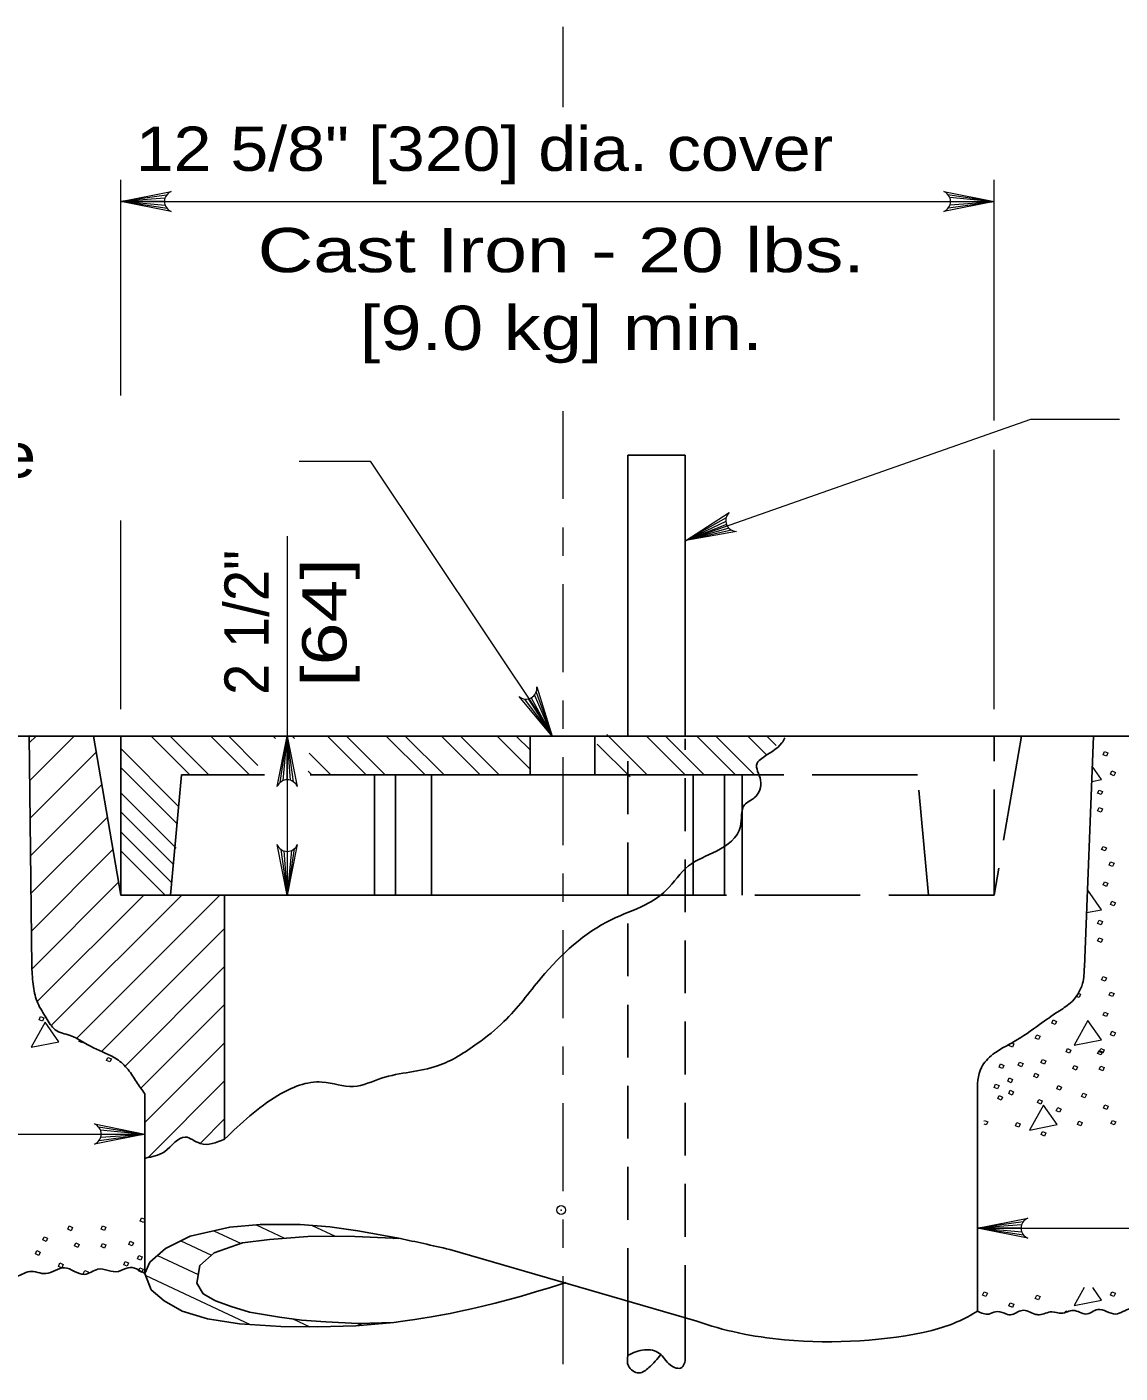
# Model space of a CAD drawing. Extents: x 1083.1 to 1117.1, y 719.4 to 741.4.
# Drawn here: x 1100.181 to 1104.035, y 731.723 to 736.468 of the extents above; entities that cross this region are included whole.
import ezdxf
from ezdxf.enums import TextEntityAlignment as Align

# ---------------------------------------------------------------- set-up
doc = ezdxf.new("R2010")
doc.units = 0
doc.header["$LTSCALE"] = 0.062
doc.header["$PDMODE"] = 32
doc.header["$PDSIZE"] = 0.031
for name, pattern in [('DOT_DASHED', [7.7, 5, -1.2, 0.3, -1.2]), ('LONG_DASHED', [7.5, 6, -1.5]), ('MEDIUM_DASHED', [4.5, 3, -1.5])]:
    doc.linetypes.add(name, pattern=pattern)
doc.layers.add('1', color=7, linetype='Continuous', lineweight=13)

msp = doc.modelspace()

# ---------------------------------------------------------------- linework, layer by layer
at = {"layer": '1'}
for p, q in [((1102.07067, 736.18433), (1102.07067, 736.46758)), ((1100.51158, 735.16817), (1100.51158, 735.92842)), ((1103.59067, 735.08033), (1103.59067, 735.92842)), ((1100.67275, 735.875), (1100.51158, 735.85242)), ((1100.66733, 735.86383), (1100.51158, 735.85242)), ((1103.42758, 735.87733), (1103.59067, 735.85242)), ((1103.43375, 735.86692), (1103.59067, 735.85242)), ((1100.51158, 735.85242), (1103.59067, 735.85242)), ((1100.66567, 735.85242), (1100.51158, 735.85242)), ((1100.6685, 735.83792), (1100.51158, 735.85242)), ((1100.67467, 735.8275), (1100.51158, 735.85242)), ((1103.4295, 735.82983), (1103.59067, 735.85242)), ((1103.43492, 735.841), (1103.59067, 735.85242)), ((1103.43658, 735.85242), (1103.59067, 735.85242)), ((1103.59067, 734.06258), (1103.59067, 734.97675)), ((1100.51158, 734.06258), (1100.51158, 734.72783)), ((1102.64525, 734.73708), (1102.50367, 734.65683)), ((1102.64433, 734.72475), (1102.50367, 734.65683)), ((1101.09833, 734.67275), (1101.09833, 733.40725)), ((1102.647, 734.7135), (1102.50367, 734.65683)), ((1102.65492, 734.70108), (1102.50367, 734.65683)), ((1102.6645, 734.69367), (1102.50367, 734.65683)), ((1101.95842, 734.103), (1102.032, 733.96767)), ((1101.96967, 734.11242), (1102.032, 733.96767)), ((1101.97592, 734.12283), (1102.032, 733.96767)), ((1101.93508, 734.0985), (1102.032, 733.96767)), ((1101.9475, 734.099), (1102.032, 733.96767)), ((1100.18842, 733.97), (1100.19267, 733.96767)), ((1100.18875, 733.94375), (1100.21267, 733.96767)), ((1100.19033, 733.811), (1100.34692, 733.96767)), ((1100.61842, 733.96767), (1100.75508, 733.831)), ((1100.68567, 733.96767), (1100.82233, 733.831)), ((1100.82908, 733.96767), (1100.96567, 733.831)), ((1100.892, 733.96767), (1100.99517, 733.86458)), ((1101.04842, 733.96767), (1101.05667, 733.95942)), ((1101.07342, 733.80458), (1101.09833, 733.96767)), ((1101.08383, 733.81075), (1101.09833, 733.96767)), ((1101.09833, 733.81367), (1101.09833, 733.96767)), ((1101.10975, 733.812), (1101.09833, 733.96767)), ((1101.12092, 733.8065), (1101.09833, 733.96767)), ((1101.1155, 733.96767), (1101.1235, 733.95967)), ((1101.24008, 733.96767), (1101.37667, 733.831)), ((1101.30717, 733.96767), (1101.44383, 733.831)), ((1101.4475, 733.96767), (1101.58417, 733.831)), ((1101.51458, 733.96767), (1101.65125, 733.831)), ((1101.642, 733.96767), (1101.77867, 733.831)), ((1101.70908, 733.96767), (1101.84575, 733.831)), ((1101.83842, 733.96767), (1101.95433, 733.85175)), ((1101.9055, 733.96767), (1101.95433, 733.91883)), ((1102.22458, 733.97342), (1102.36692, 733.831)), ((1102.36492, 733.96767), (1102.50158, 733.831)), ((1102.43208, 733.96767), (1102.56867, 733.831)), ((1102.542, 733.96767), (1102.67867, 733.831)), ((1102.60917, 733.96767), (1102.74583, 733.831)), ((1102.72183, 733.96767), (1102.78867, 733.90083)), ((1102.78892, 733.96767), (1102.82225, 733.93433)), ((1100.51158, 733.92383), (1100.7155, 733.71992)), ((1102.191, 733.93983), (1102.30692, 733.82392)), ((1100.19192, 733.67833), (1100.42533, 733.91175)), ((1101.17592, 733.90725), (1101.25217, 733.831)), ((1100.51158, 733.85658), (1100.70992, 733.65825)), ((1100.72542, 733.83042), (1100.72442, 733.8285)), ((1101.17217, 733.84392), (1101.18508, 733.831)), ((1100.19342, 733.54567), (1100.44492, 733.79708)), ((1100.51158, 733.76817), (1100.70717, 733.57258)), ((1100.195, 733.413), (1100.4645, 733.68242)), ((1100.51158, 733.70092), (1100.69708, 733.51542)), ((1100.51158, 733.63075), (1100.69125, 733.45108)), ((1100.19658, 733.28025), (1100.48408, 733.56783)), ((1100.51158, 733.5635), (1100.66783, 733.40725)), ((1101.07575, 733.56842), (1101.09833, 733.40725)), ((1101.08692, 733.563), (1101.09833, 733.40725)), ((1101.12325, 733.57033), (1101.09833, 733.40725)), ((1101.11283, 733.56417), (1101.09833, 733.40725)), ((1101.09833, 733.56133), (1101.09833, 733.40725)), ((1100.19858, 733.148), (1100.50375, 733.45308)), ((1100.21692, 733.03208), (1100.59225, 733.40725)), ((1100.2665, 732.94733), (1100.7265, 733.40725)), ((1100.35458, 732.90108), (1100.86075, 733.40725)), ((1103.92133, 733.42483), (1103.91908, 733.42075)), ((1100.44325, 732.85558), (1100.87758, 733.28975)), ((1100.52667, 732.80467), (1100.87758, 733.1555)), ((1100.58275, 732.72642), (1100.87758, 733.02125)), ((1100.59642, 732.60583), (1100.87758, 732.887)), ((1100.60867, 732.48383), (1100.87758, 732.75267)), ((1100.43333, 732.59008), (1100.59642, 732.56517)), ((1100.79142, 732.53233), (1100.87758, 732.61842)), ((1103.55483, 732.6105), (1103.55625, 732.61325)), ((1098.15858, 732.56517), (1100.59642, 732.56517)), ((1100.43525, 732.54267), (1100.59642, 732.56517)), ((1100.4395, 732.57967), (1100.59642, 732.56517)), ((1100.44067, 732.55375), (1100.59642, 732.56517)), ((1100.44233, 732.56517), (1100.59642, 732.56517)), ((1100.58508, 732.26958), (1100.59642, 732.26508)), ((1103.69258, 732.25592), (1103.53142, 732.23342)), ((1100.83983, 732.22417), (1100.93558, 732.17942)), ((1100.98858, 732.24475), (1101.08908, 732.19783)), ((1101.18608, 732.24267), (1101.26692, 732.20475)), ((1103.68708, 732.24475), (1103.53142, 732.23342)), ((1103.53142, 732.23342), (1105.67708, 732.23342)), ((1103.6855, 732.23342), (1103.53142, 732.23342)), ((1103.68833, 732.21892), (1103.53142, 732.23342)), ((1103.6945, 732.20842), (1103.53142, 732.23342)), ((1100.72325, 732.1885), (1100.83175, 732.13767)), ((1101.46542, 732.20225), (1101.47575, 732.19742)), ((1101.48958, 732.19792), (1101.49208, 732.19667)), ((1100.64125, 732.1365), (1100.78458, 732.0695)), ((1100.5995, 732.06592), (1100.96775, 731.89342)), ((1103.53133, 731.94125), (1103.53142, 731.94125)), ((1103.84067, 731.9365), (1103.843, 731.94208)), ((1103.843, 731.94208), (1103.85008, 731.93875)), ((1101.11867, 731.91325), (1101.17817, 731.88533)), ((1101.34408, 731.89792), (1101.35925, 731.89083)), ((1101.34992, 731.89783), (1101.36417, 731.89125)), ((1101.426, 731.89983), (1101.43142, 731.89733))]:
    msp.add_line(p, q, dxfattribs=at)
at = {"layer": '1', "linetype": 'DOT_DASHED'}
msp.add_line((1102.07067, 731.75358), (1102.07067, 735.13175), dxfattribs=at)
at = {"layer": '1', "lineweight": 25}
for p, q in [((1102.29925, 734.95792), (1102.50175, 734.95792)), ((1102.29925, 733.97167), (1102.29925, 734.95792)), ((1102.50175, 733.96933), (1102.50175, 734.95792)), ((1100.18842, 733.97), (1100.19808, 733.15417)), ((1100.41575, 733.96767), (1100.19267, 733.96767)), ((1103.94058, 733.96767), (1100.41575, 733.96767)), ((1100.51158, 733.40725), (1100.51158, 733.96767)), ((1101.95433, 733.831), (1101.95433, 733.96767)), ((1102.18225, 733.831), (1102.18225, 733.96767)), ((1100.68733, 733.40725), (1100.7255, 733.831)), ((1101.01833, 733.831), (1100.7255, 733.831)), ((1102.7635, 733.831), (1101.17875, 733.831)), ((1101.40542, 733.40725), (1101.40542, 733.831)), ((1101.4795, 733.40725), (1101.4795, 733.831)), ((1101.60683, 733.40725), (1101.60683, 733.831)), ((1102.52992, 733.52158), (1102.52992, 733.831)), ((1102.64008, 733.58558), (1102.64008, 733.831)), ((1102.70225, 733.6645), (1102.70225, 733.831)), ((1102.41183, 733.40725), (1100.87758, 733.40725)), ((1100.59642, 732.70692), (1100.59642, 732.48175)), ((1100.59642, 732.07317), (1100.59642, 732.48175)), ((1101.67142, 732.15792), (1102.54283, 731.9055)), ((1102.29925, 731.97708), (1102.29925, 731.78)), ((1102.50175, 731.91725), (1102.50175, 731.76733))]:
    msp.add_line(p, q, dxfattribs=at)
at = {"layer": '1', "linetype": 'MEDIUM_DASHED', "lineweight": 25}
for p, q in [((1102.29925, 731.97708), (1102.29925, 733.96033)), ((1102.50175, 731.91725), (1102.50175, 733.95808))]:
    msp.add_line(p, q, dxfattribs=at)
at = {"layer": '1', "linetype": 'LONG_DASHED', "lineweight": 25}
for p, q in [((1103.32067, 733.831), (1102.7635, 733.831)), ((1103.35883, 733.40725), (1103.32067, 733.831)), ((1102.70225, 733.40725), (1102.70225, 733.6645)), ((1102.64008, 733.40725), (1102.64008, 733.58558)), ((1102.52992, 733.40725), (1102.52992, 733.52158)), ((1103.59067, 733.40725), (1102.41183, 733.40725))]:
    msp.add_line(p, q, dxfattribs=at)
at = {"layer": '1'}
for points in [[(1100.68958, 735.81683), (1100.51158, 735.85242), (1100.68958, 735.888)], [(1103.41258, 735.888), (1103.59067, 735.85242), (1103.41258, 735.81683)], [(1102.5295, 734.66708), (1103.71983, 735.08525), (1104.03292, 735.08525)], [(1101.14017, 734.937), (1101.39058, 734.937), (1102.00717, 734.01325)], [(1102.68233, 734.68917), (1102.50367, 734.65683), (1102.65617, 734.7555)], [(1101.97817, 734.14108), (1102.032, 733.96767), (1101.91567, 734.10708)], [(1101.06275, 733.78967), (1101.09833, 733.96767), (1101.13392, 733.78967)], [(1104.00767, 733.96767), (1104.00758, 733.96758), (1104.00733, 733.96767)], [(1103.93433, 733.808), (1103.96958, 733.81492), (1103.93642, 733.86225)], [(1101.13392, 733.58525), (1101.09833, 733.40725), (1101.06275, 733.58525)], [(1103.916, 733.34558), (1103.96958, 733.356), (1103.92133, 733.42483)], [(1100.196, 733.331), (1100.19575, 733.33058), (1100.196, 733.33067)], [(1103.90867, 733.15725), (1103.91025, 733.15658), (1103.90833, 733.1525)], [(1103.88892, 733.06025), (1103.89525, 733.05767), (1103.8905, 733.04667), (1103.88125, 733.05033)], [(1100.37783, 732.88875), (1100.377, 732.88675), (1100.36508, 732.8915), (1100.3665, 732.89475)], [(1103.65292, 732.88625), (1103.65942, 732.88367), (1103.65467, 732.87175), (1103.64283, 732.87733), (1103.64442, 732.881)], [(1100.41833, 732.60075), (1100.59642, 732.56517), (1100.41833, 732.52958)], [(1103.55625, 732.61325), (1103.56808, 732.6085), (1103.56258, 732.59742), (1103.55483, 732.6005)], [(1100.59642, 732.2635), (1100.59225, 732.253), (1100.58033, 732.2585), (1100.58508, 732.26958)], [(1103.70942, 732.19775), (1103.53142, 732.23342), (1103.70942, 732.269)], [(1100.38367, 732.0705), (1100.37933, 732.07258), (1100.38492, 732.08367)], [(1100.38492, 732.08367), (1100.39675, 732.07892), (1100.39483, 732.07475)], [(1103.908, 732.02417), (1103.87225, 731.96033), (1103.96958, 731.97925), (1103.93808, 732.02417)]]:
    msp.add_lwpolyline(points, dxfattribs=at)
at = {"layer": '1', "lineweight": 25}
for points in [[(1100.19267, 733.96767), (1099.86592, 733.96767), (1099.63708, 733.6935)], [(1100.87758, 732.54725), (1100.87758, 733.40725), (1100.51158, 733.40725), (1100.41575, 733.96767)], [(1103.9085, 733.15417), (1103.94058, 733.96767), (1104.26742, 733.96767), (1104.47725, 733.6935)], [(1103.53142, 731.94125), (1103.53142, 732.02417), (1103.53142, 732.70692)], [(1101.4975, 732.19642), (1101.34708, 732.22383), (1101.249, 732.2375), (1101.14375, 732.24625), (1101.003, 732.24583), (1100.89567, 732.23708), (1100.75608, 732.20508), (1100.66917, 732.1615), (1100.61442, 732.11292), (1100.5965, 732.07325), (1100.61842, 732.0165), (1100.66483, 731.9775), (1100.72833, 731.94133), (1100.81742, 731.91392), (1100.92967, 731.89575), (1101.07542, 731.88675), (1101.20608, 731.885), (1101.33983, 731.88908), (1101.47467, 731.90117)], [(1101.47467, 731.90117), (1101.34775, 731.89783), (1101.235, 731.90292), (1101.14875, 731.90917), (1101.07117, 731.91958), (1100.96508, 731.93708), (1100.90092, 731.95675), (1100.84567, 731.9775), (1100.8015, 732.00242), (1100.77933, 732.03958), (1100.79025, 732.10158), (1100.84125, 732.14625), (1100.94075, 732.18125), (1101.03583, 732.19375), (1101.17075, 732.20408), (1101.31017, 732.20508), (1101.4975, 732.19642)]]:
    msp.add_lwpolyline(points, dxfattribs=at)
at = {"layer": '1', "linetype": 'LONG_DASHED', "lineweight": 25}
msp.add_lwpolyline([(1103.6865, 733.96767), (1103.59067, 733.40725), (1103.59067, 733.96767)], dxfattribs=at)
at = {"layer": '1'}
for points in [[(1103.97992, 733.913), (1103.99175, 733.90825), (1103.987, 733.89717), (1103.97517, 733.90192)], [(1104.006, 733.845), (1104.01792, 733.83942), (1104.01233, 733.82833), (1104.0005, 733.83308)], [(1103.96092, 733.77775), (1103.97275, 733.773), (1103.96725, 733.76192), (1103.95533, 733.76667)], [(1103.96092, 733.716), (1103.97275, 733.71125), (1103.96725, 733.69942), (1103.95533, 733.70492)], [(1103.97433, 733.57908), (1103.98625, 733.57433), (1103.9815, 733.56333), (1103.96958, 733.568)], [(1104.00125, 733.5245), (1104.01317, 733.51975), (1104.00758, 733.50867), (1103.99575, 733.51342)], [(1103.97992, 733.45408), (1103.99175, 733.44933), (1103.987, 733.43825), (1103.97517, 733.443)], [(1104.006, 733.38608), (1104.01792, 733.3805), (1104.01233, 733.36942), (1104.0005, 733.37417)], [(1103.96092, 733.31883), (1103.97275, 733.31408), (1103.96725, 733.303), (1103.95533, 733.30775)], [(1103.96092, 733.25708), (1103.97275, 733.25233), (1103.96725, 733.2405), (1103.95533, 733.246)], [(1103.97433, 733.12025), (1103.98625, 733.1155), (1103.9815, 733.10442), (1103.96958, 733.10917)], [(1104.00125, 733.06558), (1104.01317, 733.06083), (1104.00758, 733.04983), (1103.99575, 733.0545)], [(1100.22825, 732.97933), (1100.24008, 732.97458), (1100.23533, 732.96267), (1100.2235, 732.96825)], [(1103.79867, 732.9675), (1103.81058, 732.962), (1103.80583, 732.95092), (1103.79392, 732.95567)], [(1103.92133, 732.96592), (1103.87225, 732.87808), (1103.96958, 732.89708)], [(1103.97992, 732.99517), (1103.99175, 732.99042), (1103.987, 732.97942), (1103.97517, 732.98408)], [(1100.24483, 732.9595), (1100.19575, 732.87167), (1100.29308, 732.89067)], [(1104.006, 732.92717), (1104.01792, 732.92158), (1104.01233, 732.9105), (1104.0005, 732.91525)], [(1103.74092, 732.9145), (1103.75283, 732.90975), (1103.74725, 732.89867), (1103.73542, 732.90342)], [(1100.46642, 732.83533), (1100.47825, 732.83058), (1100.4735, 732.8195), (1100.46167, 732.82425)], [(1103.76117, 732.82842), (1103.773, 732.82292), (1103.7675, 732.81183), (1103.75558, 732.81733)], [(1103.849, 732.86642), (1103.86083, 732.86083), (1103.85608, 732.84983), (1103.84425, 732.85458)], [(1103.96092, 732.85992), (1103.97275, 732.85517), (1103.96725, 732.84408), (1103.95533, 732.84883)], [(1103.96692, 732.86642), (1103.97875, 732.86167), (1103.97325, 732.85058), (1103.96133, 732.85533)], [(1103.61317, 732.81258), (1103.62508, 732.80708), (1103.62033, 732.796), (1103.60842, 732.80075)], [(1103.68042, 732.81892), (1103.69233, 732.81417), (1103.68675, 732.80233), (1103.67492, 732.80783)], [(1103.73508, 732.77942), (1103.74692, 732.77383), (1103.74217, 732.76275), (1103.73033, 732.76833)], [(1103.87275, 732.80708), (1103.88458, 732.8015), (1103.87983, 732.7905), (1103.868, 732.796)], [(1103.96692, 732.80467), (1103.97875, 732.79992), (1103.97325, 732.78808), (1103.96133, 732.79358)], [(1103.59575, 732.74058), (1103.60767, 732.73583), (1103.60292, 732.72475), (1103.591, 732.7295)], [(1103.64325, 732.76275), (1103.65517, 732.75725), (1103.65042, 732.74617), (1103.6385, 732.75092)], [(1103.81575, 732.73583), (1103.82767, 732.73033), (1103.82292, 732.71925), (1103.811, 732.724)], [(1103.60842, 732.70108), (1103.62033, 732.6955), (1103.61558, 732.68442), (1103.60367, 732.69)], [(1103.64725, 732.71925), (1103.65908, 732.71367), (1103.65433, 732.70267), (1103.6425, 732.70817)], [(1103.74775, 732.68683), (1103.75958, 732.68208), (1103.75483, 732.67017), (1103.74292, 732.67575)], [(1103.90442, 732.709), (1103.91625, 732.70425), (1103.91075, 732.69233), (1103.89883, 732.69792)], [(1103.76433, 732.667), (1103.71525, 732.57917), (1103.81258, 732.59817)], [(1103.815, 732.65833), (1103.82683, 732.65275), (1103.82133, 732.64175), (1103.80942, 732.64642)], [(1103.98033, 732.66783), (1103.99225, 732.66308), (1103.9875, 732.652), (1103.97558, 732.65675)], [(1103.67092, 732.60533), (1103.68283, 732.60058), (1103.67725, 732.5895), (1103.66542, 732.59425)], [(1103.88933, 732.61008), (1103.90125, 732.60533), (1103.8965, 732.59425), (1103.88458, 732.599)], [(1104.00725, 732.61325), (1104.01908, 732.6085), (1104.01358, 732.59742), (1104.00175, 732.60217)], [(1103.76117, 732.57442), (1103.773, 732.56967), (1103.76825, 732.55783), (1103.75642, 732.56342)], [(1100.3295, 732.24108), (1100.34133, 732.23558), (1100.33658, 732.2245), (1100.32475, 732.22925)], [(1100.44742, 732.24108), (1100.45925, 732.23633), (1100.45375, 732.22525), (1100.44183, 732.23)], [(1100.24167, 732.20308), (1100.2535, 732.19758), (1100.248, 732.1865), (1100.23617, 732.19208)], [(1100.35325, 732.18175), (1100.36508, 732.17625), (1100.36033, 732.16517), (1100.3485, 732.17067)], [(1100.44742, 732.17942), (1100.45925, 732.17467), (1100.45375, 732.16275), (1100.44183, 732.16833)], [(1100.54475, 732.18733), (1100.55658, 732.18175), (1100.55183, 732.17067), (1100.54, 732.17542)], [(1100.21558, 732.15408), (1100.22742, 732.1485), (1100.22267, 732.13742), (1100.21083, 732.143)], [(1100.29625, 732.11058), (1100.30817, 732.105), (1100.30342, 732.09392), (1100.2915, 732.09867)], [(1100.52733, 732.11533), (1100.53917, 732.11058), (1100.53442, 732.0995), (1100.52258, 732.10425)], [(1100.57483, 732.13742), (1100.58667, 732.13192), (1100.58192, 732.12083), (1100.57008, 732.12558)], [(1100.57875, 732.09392), (1100.59067, 732.08842), (1100.58592, 732.07733), (1100.574, 732.08283)], [(1103.555, 732.00933), (1103.56683, 732.00383), (1103.56133, 731.99275), (1103.54942, 731.9975)], [(1103.64758, 731.97058), (1103.65942, 731.96583), (1103.65467, 731.954), (1103.64283, 731.9595)], [(1103.74092, 731.99667), (1103.75283, 731.99192), (1103.74725, 731.98083), (1103.73542, 731.98558)], [(1104.006, 732.00933), (1104.01792, 732.00383), (1104.01233, 731.99275), (1104.0005, 731.9975)]]:
    msp.add_lwpolyline(points, close=True, dxfattribs=at)
for centre, major_axis, start_param, end_param in [((1100.70407, 735.85242), (-0.03843, 0), 5.0978942, 7.4685073), ((1103.39817, 735.85242), (0.03843, 0), 5.0978942, 7.4685073), ((1102.68269, 734.72765), (-0.03625, -0.01274), 5.1365998, 7.5072129), ((1101.94001, 734.13676), (-0.03843, 0), 0.8835974, 3.2542105), ((1101.09832, 733.77521), (0.03843, 0), 0.3855052, 2.7561184), ((1101.09832, 733.59974), (-0.03843, 0), 0.3855052, 2.7561184), ((1100.40391, 732.56518), (0.03843, 0), 5.0978942, 7.4685073), ((1103.72388, 732.23338), (-0.03843, 0), 5.0978942, 7.4685073)]:
    msp.add_ellipse(centre, major_axis=major_axis, ratio=0.999895, start_param=start_param, end_param=end_param, dxfattribs=at)
at = {"layer": '1', "lineweight": 25}
for centre, major_axis, start_param, end_param in [((1103.12612, 732.07329), (0.49387, 0), 5.2308377, 5.6746503), ((1102.995, 732.1793), (-0.73959, 0), 0.9130573, 1.3757934), ((1103.00777, 732.21583), (-0.81859, 0), 1.3789738, 2.0303511)]:
    msp.add_ellipse(centre, major_axis=major_axis, ratio=0.467827, start_param=start_param, end_param=end_param, dxfattribs=at)
for points in [[(1102.85292, 733.96175), (1102.84217, 733.94383), (1102.77133, 733.88933), (1102.75508, 733.87217), (1102.76733, 733.81217), (1102.745, 733.75067), (1102.71092, 733.7255), (1102.69625, 733.64917), (1102.61192, 733.56275), (1102.513, 733.51), (1102.43442, 733.42433), (1102.3605, 733.37317), (1102.24233, 733.3215), (1101.99375, 733.11558), (1101.8625, 732.96125), (1101.768, 732.884), (1101.62833, 732.80533), (1101.43067, 732.76167), (1101.33233, 732.73283), (1101.22158, 732.7485), (1101.06558, 732.70117), (1100.87758, 732.54725)], [(1100.19808, 733.15417), (1100.20358, 733.08467), (1100.21908, 733.02592), (1100.24875, 732.97467), (1100.28025, 732.93292), (1100.33358, 732.91217), (1100.4155, 732.86883), (1100.49733, 732.82917), (1100.53733, 732.79225), (1100.56708, 732.74867), (1100.59642, 732.70692)], [(1103.53142, 732.70692), (1103.54567, 732.7995), (1103.58625, 732.84625), (1103.661, 732.89108), (1103.751, 732.95125), (1103.81533, 732.99617), (1103.85883, 733.02667), (1103.90217, 733.09617), (1103.9085, 733.15417)], [(1100.5985, 732.48042), (1100.66508, 732.50267), (1100.73908, 732.5545), (1100.79083, 732.53225), (1100.87758, 732.54725)], [(1099.65058, 732.07317), (1099.69125, 732.0625), (1099.71475, 732.07033), (1099.74608, 732.06517), (1099.767, 732.05992), (1099.80875, 732.07558), (1099.85317, 732.0625), (1099.86883, 732.05992), (1099.91317, 732.07033), (1099.94717, 732.06517), (1099.98892, 732.07558), (1100.03333, 732.0625), (1100.07508, 732.07817), (1100.13775, 732.0625), (1100.19, 732.08083), (1100.24742, 732.073), (1100.31275, 732.09383), (1100.38325, 732.07033), (1100.43033, 732.08867), (1100.50342, 732.08083), (1100.53733, 732.09383), (1100.5965, 732.07317)], [(1104.47725, 731.94125), (1104.41808, 731.96192), (1104.38417, 731.94892), (1104.31108, 731.95675), (1104.264, 731.9385), (1104.1935, 731.96192), (1104.12817, 731.94108), (1104.07075, 731.94892), (1104.0185, 731.93058), (1103.95583, 731.94633), (1103.91408, 731.93058), (1103.86967, 731.94367), (1103.82792, 731.93325), (1103.79392, 731.9385), (1103.74958, 731.928), (1103.73392, 731.93058), (1103.6895, 731.94367), (1103.64775, 731.928), (1103.62683, 731.93325), (1103.5955, 731.9385), (1103.572, 731.93058), (1103.53133, 731.94125)], [(1102.29925, 731.78533), (1102.30117, 731.748), (1102.33875, 731.72283), (1102.37317, 731.74167), (1102.41608, 731.78867)], [(1102.50175, 731.76733), (1102.48908, 731.74167), (1102.44842, 731.75108), (1102.41083, 731.79192), (1102.3575, 731.80442), (1102.29925, 731.78533)]]:
    msp.add_spline(points, degree=3, dxfattribs=at)
for points in [[(1101.67142, 732.15792), (1101.60725, 732.17317), (1101.54942, 732.18575), (1101.4975, 732.19642)], [(1101.47467, 731.90117), (1101.59192, 731.91542), (1101.78, 731.94517), (1102.082, 732.04167)]]:
    msp.add_open_spline(points, degree=3, dxfattribs=at)
at = {"layer": '1'}
msp.add_point((1102.06392, 732.29725), dxfattribs=at)

# ---------------------------------------------------------------- texts
for s, width, p in [('12 5/8" [320] dia. cover', 1.15, (1100.56433, 735.96017)), ('1" [25] dia. lift hole', 1.2, (1098.16275, 734.87942))]:
    msp.add_text(s, height=0.156, dxfattribs=dict(at, width=width)).set_placement(p)
for s, width, p in [('Cast Iron - 20 lbs.', 1.3, (1102.06429, 735.603)), ('[9.0 kg] min.', 1.25, (1102.06433, 735.329))]:
    msp.add_text(s, height=0.156, dxfattribs=dict(at, width=width)).set_placement(p, align=Align.CENTER)
for s, width, p in [('2 1/2"', 0.95, (1101.033, 734.36829)), ('[64]', 1.3, (1101.307, 734.36825))]:
    msp.add_text(s, height=0.156, rotation=90, dxfattribs=dict(at, width=width)).set_placement(p, align=Align.CENTER)

doc.saveas('drawing.dxf')
